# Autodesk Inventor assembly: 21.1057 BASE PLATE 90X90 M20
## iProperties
Created: 2007-03
Part Number: 21.1057 BASE PLATE 90X90 M20
Document SubType Name: Assembly
Designer: Andy Moles
Author: Andy Moles
